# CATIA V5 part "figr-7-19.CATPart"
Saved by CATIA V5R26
Part number: Part2
Bounding box of the stored display mesh (mm): x -50 to 50, y -65 to 65, z 0 to 28
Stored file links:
  D:\_Deepak\CATIA\CATIA V5-6R2016_Deepak\Resources\Part files\Partfiles\c07_catia_v5_6r2016_prt\figr-7-19.CATPart
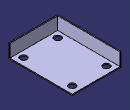
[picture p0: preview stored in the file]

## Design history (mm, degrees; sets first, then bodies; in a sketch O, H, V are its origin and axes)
Body1 (main body)
  Sketch1 on xy-plane, origin (0, 0, 0), H (1, 0, 0), V (0, 1, 0)
    line L1 (-50, 65) -> (50, 65)
    line L2 (50, 65) -> (50, -65)
    line L3 (50, -65) -> (-50, -65)
    line L4 (-50, -65) -> (-50, 65)
    axis line L5 (50, -65) -> (-50, 65)
    length L3 = 100
    length L2 = 130
    horizontal: L1 H, L3 H
    vertical: L2 V, L4 V
    midpoint: O L5
  Pad1: profile Sketch1, direction (0, 0, 1), length 28
  Shell1: ExtOffset 0, Face (face of Pad1; face of Pad1; face of Pad1), IntOffset 2
  Sketch2 on face of Pad1, origin (25.9302, -33.7092, 28), H (1, 0, 0), V (0, 1, 0)
    point P1 (9.0698, -16.2908)
    reference projected line E1 (-75.9302, -31.2908) -> (24.0698, -31.2908) from edge [face of Pad1 | face of Pad1]
    reference projected line E2 (24.0698, -31.2908) -> (24.0698, 98.7092) from edge [face of Pad1 | face of Pad1]
    distance P1 E1 = 15
    distance P1 E2 = 15
  Hole1: placed by Sketch2, at (35, -50, 28) direction (0, 0, -1), diameter 14, through (limit type 3)
  RectPattern1: of Hole1, direction 1 instances 2, spacing 100, along edge [face of Pad1 | face of Pad1], direction 2 instances 2, spacing 70, along edge [face of Pad1 | face of Pad1]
